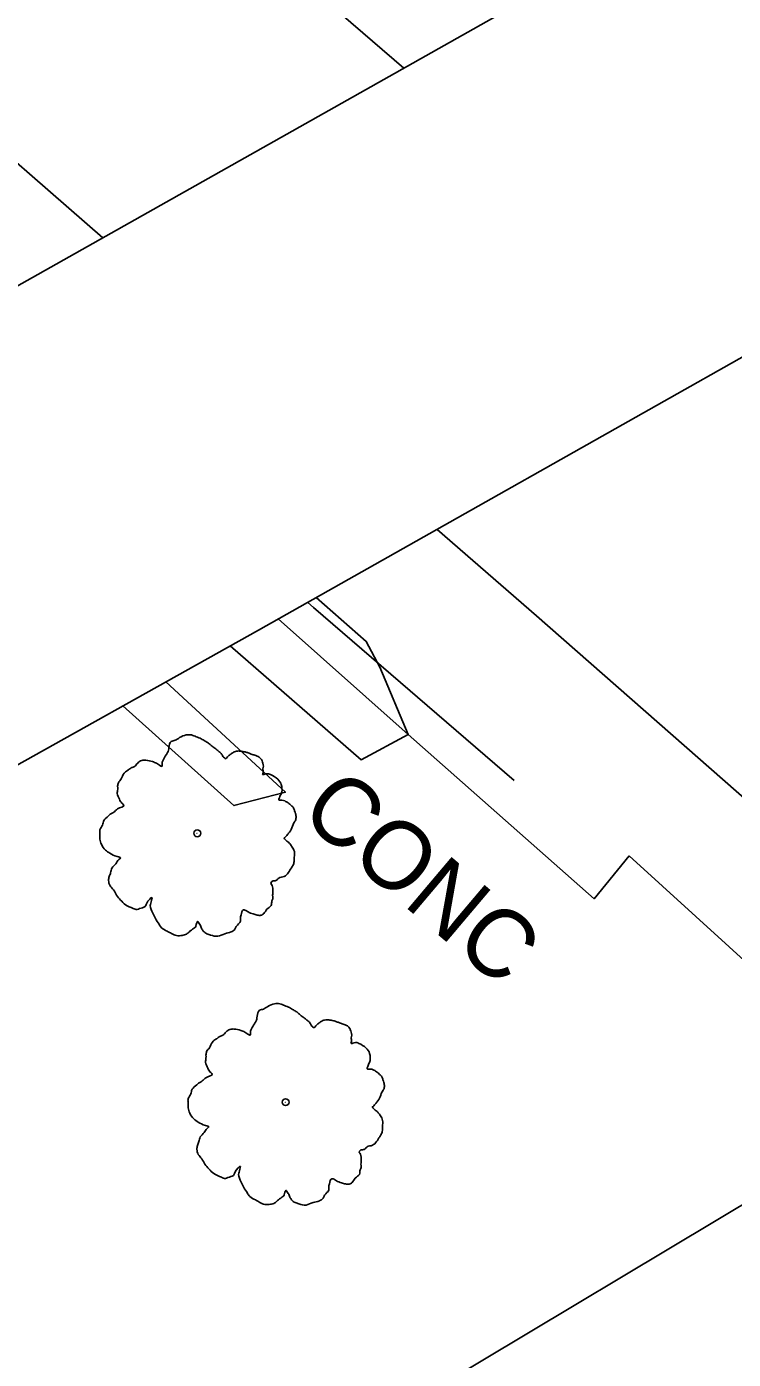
# Model space of a CAD drawing. Extents: x 2076109 to 2080761, y 592812 to 596750.
# Drawn here: x 2077233.4 to 2077285.2, y 595674.8 to 595772.6 of the extents above; entities that cross this region are included whole.
import ezdxf

# ---------------------------------------------------------------- set-up
doc = ezdxf.new("R2010")
doc.units = 0
for name, color, linetype in [('Default', 7, 'Continuous'), ('RD_EX_Bridge', 7, 'Continuous'), ('RD_EX_Conc', 7, 'Continuous'), ('RD_EX_Conc_txCode', 7, 'Continuous'), ('RD_EX_GuardRail', 7, 'Continuous'), ('RD_EX_Misc', 7, 'Continuous'), ('RD_EX_Road', 7, 'Continuous'), ('RD_EX_UT', 7, 'Continuous'), ('RD_EX_VEG', 7, 'Continuous')]:
    doc.layers.add(name, color=color, linetype=linetype)

msp = doc.modelspace()

# ---------------------------------------------------------------- linework, layer by layer
at = {"layer": 'Default'}
msp.add_arc((2035586.697, 547847.965), 63546.515, 48.5011873, 49.29231256, dxfattribs=at)
msp.add_arc((2035586.697, 547847.965), 63546.515, 48.5011873, 49.29231256, dxfattribs=at)
at = {"layer": 'RD_EX_Bridge'}
msp.add_lwpolyline([(2077182.691, 595725.558), (2077226.255, 595749.947), (2077278.629, 595779.435), (2077318.688, 595801.87), (2077370.979, 595831.152), (2077414.589, 595855.594), (2077438.976, 595834.259), (2077395.397, 595809.745), (2077342.887, 595780.396), (2077302.728, 595757.837), (2077250.382, 595728.313), (2077206.947, 595704.058)], close=True, dxfattribs=at)
msp.add_lwpolyline([(2077182.691, 595725.558), (2077226.255, 595749.947), (2077278.629, 595779.435), (2077318.688, 595801.87), (2077370.979, 595831.152), (2077414.589, 595855.594), (2077438.976, 595834.259), (2077395.397, 595809.745), (2077342.887, 595780.396), (2077302.728, 595757.837), (2077250.382, 595728.313), (2077206.947, 595704.058)], close=True, dxfattribs=at)
at = {"layer": 'RD_EX_Conc'}
for points in [[(2077251.831, 595729.131), (2077261.361, 595720.667), (2077257.913, 595718.805), (2077248.302, 595727.152)], [(2077251.831, 595729.131), (2077261.361, 595720.667), (2077257.913, 595718.805), (2077248.302, 595727.152)], [(2077243.58, 595724.515), (2077252.348, 595716.428), (2077248.572, 595715.442), (2077240.424, 595722.752)], [(2077243.58, 595724.515), (2077252.348, 595716.428), (2077248.572, 595715.442), (2077240.424, 595722.752)]]:
    msp.add_lwpolyline(points, dxfattribs=at)
at = {"layer": 'RD_EX_GuardRail'}
msp.add_lwpolyline([(2077253.991, 595730.349), (2077254.423, 595729.975), (2077269.145, 595717.286)], dxfattribs=at)
msp.add_lwpolyline([(2077253.991, 595730.349), (2077254.423, 595729.975), (2077269.145, 595717.286)], dxfattribs=at)
at = {"layer": 'RD_EX_Misc'}
for points in [[(2076740.943, 596217.329), (2076779.876, 596183.766), (2076827.317, 596143.014), (2076861.064, 596114.091), (2076898.336, 596082.262), (2076930.168, 596054.828), (2076977.991, 596013.659), (2077013.095, 595983.674), (2077050.747, 595951.153), (2077080.277, 595925.677), (2077141.218, 595873.032), (2077167.07, 595850.498), (2077217.753, 595806.944), (2077236.465, 595790.711), (2077261.034, 595769.528)], [(2076740.943, 596217.329), (2076779.876, 596183.766), (2076827.317, 596143.014), (2076861.064, 596114.091), (2076898.336, 596082.262), (2076930.168, 596054.828), (2076977.991, 596013.659), (2077013.095, 595983.674), (2077050.747, 595951.153), (2077080.277, 595925.677), (2077141.218, 595873.032), (2077167.07, 595850.498), (2077217.753, 595806.944), (2077236.465, 595790.711), (2077261.034, 595769.528)], [(2077238.942, 595757.089), (2077227.218, 595767.306), (2077200.966, 595789.857), (2077174.304, 595812.849), (2077143.562, 595839.448), (2077119.234, 595860.41), (2077093.272, 595882.761), (2077072.458, 595900.642), (2077047.169, 595922.374), (2077020.069, 595945.554), (2076995.162, 595967.193), (2076973.205, 595985.954), (2076950.941, 596005.114), (2076925.457, 596027.104), (2076903.871, 596045.596), (2076877.623, 596068.098), (2076855.077, 596087.36), (2076831.502, 596107.635), (2076806.015, 596129.351), (2076775.579, 596155.551), (2076743.515, 596183.091), (2076721.01, 596202.456)], [(2077238.942, 595757.089), (2077227.218, 595767.306), (2077200.966, 595789.857), (2077174.304, 595812.849), (2077143.562, 595839.448), (2077119.234, 595860.41), (2077093.272, 595882.761), (2077072.458, 595900.642), (2077047.169, 595922.374), (2077020.069, 595945.554), (2076995.162, 595967.193), (2076973.205, 595985.954), (2076950.941, 596005.114), (2076925.457, 596027.104), (2076903.871, 596045.596), (2076877.623, 596068.098), (2076855.077, 596087.36), (2076831.502, 596107.635), (2076806.015, 596129.351), (2076775.579, 596155.551), (2076743.515, 596183.091), (2076721.01, 596202.456)], [(2077294.469, 595708.577), (2077270.768, 595729.355), (2077263.484, 595735.703)], [(2077294.469, 595708.577), (2077270.768, 595729.355), (2077263.484, 595735.703)]]:
    msp.add_lwpolyline(points, dxfattribs=at)
at = {"layer": 'RD_EX_Road'}
for points in [[(2077277.578, 595711.76), (2077274.998, 595708.61), (2077261.361, 595720.667), (2077259.291, 595725.609), (2077258.28, 595727.485), (2077254.611, 595730.699)], [(2077277.578, 595711.76), (2077274.998, 595708.61), (2077261.361, 595720.667), (2077259.291, 595725.609), (2077258.28, 595727.485), (2077254.611, 595730.699)], [(2077277.578, 595711.76), (2077294.436, 595696.437)], [(2077277.578, 595711.76), (2077294.436, 595696.437)]]:
    msp.add_lwpolyline(points, dxfattribs=at)
at = {"layer": 'RD_EX_UT'}
msp.add_line((2077214.8, 595643.674), (2077512.893, 595821.921), dxfattribs=at)
msp.add_line((2077214.8, 595643.674), (2077512.893, 595821.921), dxfattribs=at)
at = {"layer": 'RD_EX_VEG'}
for centre, radius in [((2077245.885, 595713.416), 0.25), ((2077245.885, 595713.416), 0.25), ((2077245.864, 595713.41), 0.0001), ((2077245.864, 595713.41), 0.0001), ((2077252.366, 595693.701), 0.25), ((2077252.366, 595693.701), 0.25), ((2077252.345, 595693.695), 0.0001), ((2077252.345, 595693.695), 0.0001)]:
    msp.add_circle(centre, radius, dxfattribs=at)
for points in [[(2077250.628, 595718.791), (2077250.416, 595719.004), (2077250.104, 595719.138), (2077249.849, 595719.224), (2077249.629, 595719.313), (2077249.393, 595719.382), (2077249.051, 595719.443), (2077248.75, 595719.437), (2077248.493, 595719.327), (2077248.309, 595719.188), (2077248.093, 595719.011), (2077247.98, 595718.878), (2077247.869, 595718.94), (2077247.77, 595719.056), (2077247.629, 595719.275), (2077247.438, 595719.437), (2077247.248, 595719.599), (2077246.965, 595719.806), (2077246.699, 595720.033), (2077246.457, 595720.173), (2077246.177, 595720.345), (2077245.811, 595720.493), (2077245.463, 595720.624), (2077245.073, 595720.628), (2077244.575, 595720.428), (2077244.253, 595720.243), (2077243.977, 595720.149), (2077243.8, 595719.71), (2077243.706, 595719.33), (2077243.596, 595719.161), (2077243.378, 595718.789), (2077243.308, 595718.553), (2077243.274, 595718.32), (2077243.201, 595718.349), (2077242.883, 595718.554), (2077242.59, 595718.672), (2077242.12, 595718.776), (2077241.803, 595718.75), (2077241.517, 595718.568), (2077241.271, 595718.317), (2077241.065, 595718.23), (2077240.83, 595718.069), (2077240.763, 595718.028), (2077240.514, 595717.813), (2077240.299, 595717.405), (2077240.091, 595717.123), (2077240.041, 595716.87), (2077240.042, 595716.64), (2077240.013, 595716.336), (2077240.172, 595715.906), (2077240.355, 595715.619), (2077240.491, 595715.471), (2077240.034, 595715.203), (2077239.769, 595714.969), (2077239.415, 595714.746), (2077239.367, 595714.688), (2077239.021, 595714.359), (2077238.925, 595714.014), (2077238.739, 595713.68), (2077238.727, 595713.396), (2077238.742, 595712.989), (2077238.844, 595712.607), (2077239.143, 595712.188), (2077239.464, 595711.949), (2077240.015, 595711.709), (2077240.254, 595711.605), (2077240.122, 595711.488), (2077239.898, 595711.186), (2077239.623, 595710.862), (2077239.527, 595710.518), (2077239.425, 595710.244), (2077239.377, 595709.956), (2077239.479, 595709.574), (2077239.735, 595709.258), (2077239.962, 595708.869), (2077240.256, 595708.52), (2077240.62, 595708.177), (2077241.174, 595707.903), (2077241.465, 595707.82), (2077241.654, 595707.889), (2077242.049, 595708.045), (2077242.157, 595708.249), (2077242.564, 595708.689), (2077242.527, 595708.491), (2077242.434, 595708.112), (2077242.62, 595707.559), (2077242.812, 595707.167), (2077243.076, 595706.745), (2077243.256, 595706.494), (2077243.666, 595706.244), (2077244.001, 595706.058), (2077244.367, 595705.91), (2077244.774, 595705.925), (2077245.085, 595706.022), (2077245.301, 595706.199), (2077245.601, 595706.436), (2077245.752, 595706.536)], [(2077250.628, 595718.791), (2077250.416, 595719.004), (2077250.104, 595719.138), (2077249.849, 595719.224), (2077249.629, 595719.313), (2077249.393, 595719.382), (2077249.051, 595719.443), (2077248.75, 595719.437), (2077248.493, 595719.327), (2077248.309, 595719.188), (2077248.093, 595719.011), (2077247.98, 595718.878), (2077247.869, 595718.94), (2077247.77, 595719.056), (2077247.629, 595719.275), (2077247.438, 595719.437), (2077247.248, 595719.599), (2077246.965, 595719.806), (2077246.699, 595720.033), (2077246.457, 595720.173), (2077246.177, 595720.345), (2077245.811, 595720.493), (2077245.463, 595720.624), (2077245.073, 595720.628), (2077244.575, 595720.428), (2077244.253, 595720.243), (2077243.977, 595720.149), (2077243.8, 595719.71), (2077243.706, 595719.33), (2077243.596, 595719.161), (2077243.378, 595718.789), (2077243.308, 595718.553), (2077243.274, 595718.32), (2077243.201, 595718.349), (2077242.883, 595718.554), (2077242.59, 595718.672), (2077242.12, 595718.776), (2077241.803, 595718.75), (2077241.517, 595718.568), (2077241.271, 595718.317), (2077241.065, 595718.23), (2077240.83, 595718.069), (2077240.763, 595718.028), (2077240.514, 595717.813), (2077240.299, 595717.405), (2077240.091, 595717.123), (2077240.041, 595716.87), (2077240.042, 595716.64), (2077240.013, 595716.336), (2077240.172, 595715.906), (2077240.355, 595715.619), (2077240.491, 595715.471), (2077240.034, 595715.203), (2077239.769, 595714.969), (2077239.415, 595714.746), (2077239.367, 595714.688), (2077239.021, 595714.359), (2077238.925, 595714.014), (2077238.739, 595713.68), (2077238.727, 595713.396), (2077238.742, 595712.989), (2077238.844, 595712.607), (2077239.143, 595712.188), (2077239.464, 595711.949), (2077240.015, 595711.709), (2077240.254, 595711.605), (2077240.122, 595711.488), (2077239.898, 595711.186), (2077239.623, 595710.862), (2077239.527, 595710.518), (2077239.425, 595710.244), (2077239.377, 595709.956), (2077239.479, 595709.574), (2077239.735, 595709.258), (2077239.962, 595708.869), (2077240.256, 595708.52), (2077240.62, 595708.177), (2077241.174, 595707.903), (2077241.465, 595707.82), (2077241.654, 595707.889), (2077242.049, 595708.045), (2077242.157, 595708.249), (2077242.564, 595708.689), (2077242.527, 595708.491), (2077242.434, 595708.112), (2077242.62, 595707.559), (2077242.812, 595707.167), (2077243.076, 595706.745), (2077243.256, 595706.494), (2077243.666, 595706.244), (2077244.001, 595706.058), (2077244.367, 595705.91), (2077244.774, 595705.925), (2077245.085, 595706.022), (2077245.301, 595706.199), (2077245.601, 595706.436), (2077245.752, 595706.536)], [(2077245.752, 595706.536), (2077245.809, 595706.718), (2077245.932, 595706.941), (2077245.973, 595706.873), (2077246.074, 595706.722), (2077246.203, 595706.449), (2077246.326, 595706.246), (2077246.589, 595706.055), (2077246.863, 595705.953), (2077247.384, 595705.871), (2077247.901, 595706.054), (2077248.369, 595706.181), (2077248.637, 595706.38), (2077248.745, 595706.584), (2077249.049, 595706.981), (2077249.059, 595707.3), (2077249.102, 595707.428), (2077249.284, 595707.797), (2077249.374, 595707.787), (2077249.616, 595707.647), (2077249.982, 595707.499), (2077250.273, 595707.416), (2077250.557, 595707.404), (2077250.76, 595707.527), (2077251, 595707.848), (2077251.297, 595708.12), (2077251.337, 595708.283), (2077251.358, 595708.462), (2077251.43, 595708.663), (2077251.413, 595708.874), (2077251.434, 595709.053), (2077251.423, 595709.194), (2077251.425, 595709.389), (2077251.373, 595709.597), (2077251.291, 595709.733), (2077251.35, 595709.879), (2077251.593, 595709.934), (2077251.696, 595709.978), (2077251.861, 595710.133), (2077252.259, 595710.254), (2077252.556, 595710.526), (2077252.793, 595710.882), (2077252.933, 595711.124), (2077252.997, 595711.431), (2077253.007, 595711.751), (2077253.025, 595711.965), (2077252.972, 595712.173), (2077252.806, 595712.479), (2077252.648, 595712.679), (2077252.381, 595712.905), (2077252.261, 595713.073), (2077252.313, 595713.095), (2077252.41, 595713.209), (2077252.588, 595713.419), (2077252.822, 595713.81), (2077253.032, 595714.288), (2077253.048, 595714.307), (2077253.133, 595714.562), (2077253.092, 595714.86), (2077253.023, 595715.049), (2077252.952, 595715.274), (2077252.778, 595715.455), (2077252.549, 595715.649), (2077252.307, 595715.789), (2077252.09, 595715.842), (2077251.876, 595715.861), (2077251.916, 595716.023), (2077252.034, 595716.317), (2077252.093, 595716.463), (2077252.092, 595716.693), (2077252.05, 595716.991), (2077251.789, 595717.378), (2077251.264, 595717.726), (2077250.906, 595717.768), (2077250.679, 595717.731), (2077250.722, 595717.859), (2077250.699, 595718.141), (2077250.736, 595718.339), (2077250.684, 595718.547), (2077250.634, 595718.721), (2077250.59, 595718.823)], [(2077245.752, 595706.536), (2077245.809, 595706.718), (2077245.932, 595706.941), (2077245.973, 595706.873), (2077246.074, 595706.722), (2077246.203, 595706.449), (2077246.326, 595706.246), (2077246.589, 595706.055), (2077246.863, 595705.953), (2077247.384, 595705.871), (2077247.901, 595706.054), (2077248.369, 595706.181), (2077248.637, 595706.38), (2077248.745, 595706.584), (2077249.049, 595706.981), (2077249.059, 595707.3), (2077249.102, 595707.428), (2077249.284, 595707.797), (2077249.374, 595707.787), (2077249.616, 595707.647), (2077249.982, 595707.499), (2077250.273, 595707.416), (2077250.557, 595707.404), (2077250.76, 595707.527), (2077251, 595707.848), (2077251.297, 595708.12), (2077251.337, 595708.283), (2077251.358, 595708.462), (2077251.43, 595708.663), (2077251.413, 595708.874), (2077251.434, 595709.053), (2077251.423, 595709.194), (2077251.425, 595709.389), (2077251.373, 595709.597), (2077251.291, 595709.733), (2077251.35, 595709.879), (2077251.593, 595709.934), (2077251.696, 595709.978), (2077251.861, 595710.133), (2077252.259, 595710.254), (2077252.556, 595710.526), (2077252.793, 595710.882), (2077252.933, 595711.124), (2077252.997, 595711.431), (2077253.007, 595711.751), (2077253.025, 595711.965), (2077252.972, 595712.173), (2077252.806, 595712.479), (2077252.648, 595712.679), (2077252.381, 595712.905), (2077252.261, 595713.073), (2077252.313, 595713.095), (2077252.41, 595713.209), (2077252.588, 595713.419), (2077252.822, 595713.81), (2077253.032, 595714.288), (2077253.048, 595714.307), (2077253.133, 595714.562), (2077253.092, 595714.86), (2077253.023, 595715.049), (2077252.952, 595715.274), (2077252.778, 595715.455), (2077252.549, 595715.649), (2077252.307, 595715.789), (2077252.09, 595715.842), (2077251.876, 595715.861), (2077251.916, 595716.023), (2077252.034, 595716.317), (2077252.093, 595716.463), (2077252.092, 595716.693), (2077252.05, 595716.991), (2077251.789, 595717.378), (2077251.264, 595717.726), (2077250.906, 595717.768), (2077250.679, 595717.731), (2077250.722, 595717.859), (2077250.699, 595718.141), (2077250.736, 595718.339), (2077250.684, 595718.547), (2077250.634, 595718.721), (2077250.59, 595718.823)], [(2077257.109, 595699.076), (2077256.897, 595699.29), (2077256.585, 595699.424), (2077256.33, 595699.51), (2077256.11, 595699.598), (2077255.874, 595699.668), (2077255.532, 595699.729), (2077255.231, 595699.722), (2077254.974, 595699.613), (2077254.79, 595699.474), (2077254.574, 595699.297), (2077254.461, 595699.163), (2077254.35, 595699.225), (2077254.251, 595699.341), (2077254.11, 595699.56), (2077253.919, 595699.722), (2077253.729, 595699.884), (2077253.446, 595700.092), (2077253.18, 595700.318), (2077252.938, 595700.458), (2077252.658, 595700.631), (2077252.292, 595700.778), (2077251.944, 595700.91), (2077251.554, 595700.913), (2077251.056, 595700.714), (2077250.734, 595700.528), (2077250.458, 595700.435), (2077250.281, 595699.995), (2077250.187, 595699.615), (2077250.077, 595699.447), (2077249.859, 595699.074), (2077249.789, 595698.838), (2077249.755, 595698.605), (2077249.682, 595698.635), (2077249.364, 595698.839), (2077249.071, 595698.957), (2077248.601, 595699.061), (2077248.284, 595699.036), (2077247.998, 595698.853), (2077247.752, 595698.602), (2077247.547, 595698.515), (2077247.311, 595698.354), (2077247.244, 595698.313), (2077246.995, 595698.098), (2077246.78, 595697.691), (2077246.572, 595697.408), (2077246.522, 595697.156), (2077246.523, 595696.925), (2077246.494, 595696.622), (2077246.653, 595696.191), (2077246.836, 595695.905), (2077246.972, 595695.756), (2077246.515, 595695.489), (2077246.25, 595695.255), (2077245.896, 595695.031), (2077245.848, 595694.974), (2077245.502, 595694.644), (2077245.406, 595694.3), (2077245.22, 595693.966), (2077245.208, 595693.681), (2077245.223, 595693.274), (2077245.325, 595692.893), (2077245.624, 595692.474), (2077245.945, 595692.234), (2077246.496, 595691.995), (2077246.735, 595691.89), (2077246.603, 595691.773), (2077246.379, 595691.471), (2077246.104, 595691.148), (2077246.008, 595690.803), (2077245.906, 595690.529), (2077245.858, 595690.241), (2077245.96, 595689.86), (2077246.216, 595689.543), (2077246.443, 595689.154), (2077246.737, 595688.806), (2077247.101, 595688.463), (2077247.655, 595688.188), (2077247.946, 595688.106), (2077248.135, 595688.174), (2077248.53, 595688.33), (2077248.638, 595688.534), (2077249.045, 595688.975), (2077249.008, 595688.777), (2077248.915, 595688.397), (2077249.101, 595687.845), (2077249.293, 595687.452), (2077249.557, 595687.031), (2077249.737, 595686.779), (2077250.147, 595686.529), (2077250.482, 595686.343), (2077250.848, 595686.196), (2077251.255, 595686.211), (2077251.566, 595686.307), (2077251.782, 595686.484), (2077252.082, 595686.721), (2077252.233, 595686.822)], [(2077257.109, 595699.076), (2077256.897, 595699.29), (2077256.585, 595699.424), (2077256.33, 595699.51), (2077256.11, 595699.598), (2077255.874, 595699.668), (2077255.532, 595699.729), (2077255.231, 595699.722), (2077254.974, 595699.613), (2077254.79, 595699.474), (2077254.574, 595699.297), (2077254.461, 595699.163), (2077254.35, 595699.225), (2077254.251, 595699.341), (2077254.11, 595699.56), (2077253.919, 595699.722), (2077253.729, 595699.884), (2077253.446, 595700.092), (2077253.18, 595700.318), (2077252.938, 595700.458), (2077252.658, 595700.631), (2077252.292, 595700.778), (2077251.944, 595700.91), (2077251.554, 595700.913), (2077251.056, 595700.714), (2077250.734, 595700.528), (2077250.458, 595700.435), (2077250.281, 595699.995), (2077250.187, 595699.615), (2077250.077, 595699.447), (2077249.859, 595699.074), (2077249.789, 595698.838), (2077249.755, 595698.605), (2077249.682, 595698.635), (2077249.364, 595698.839), (2077249.071, 595698.957), (2077248.601, 595699.061), (2077248.284, 595699.036), (2077247.998, 595698.853), (2077247.752, 595698.602), (2077247.547, 595698.515), (2077247.311, 595698.354), (2077247.244, 595698.313), (2077246.995, 595698.098), (2077246.78, 595697.691), (2077246.572, 595697.408), (2077246.522, 595697.156), (2077246.523, 595696.925), (2077246.494, 595696.622), (2077246.653, 595696.191), (2077246.836, 595695.905), (2077246.972, 595695.756), (2077246.515, 595695.489), (2077246.25, 595695.255), (2077245.896, 595695.031), (2077245.848, 595694.974), (2077245.502, 595694.644), (2077245.406, 595694.3), (2077245.22, 595693.966), (2077245.208, 595693.681), (2077245.223, 595693.274), (2077245.325, 595692.893), (2077245.624, 595692.474), (2077245.945, 595692.234), (2077246.496, 595691.995), (2077246.735, 595691.89), (2077246.603, 595691.773), (2077246.379, 595691.471), (2077246.104, 595691.148), (2077246.008, 595690.803), (2077245.906, 595690.529), (2077245.858, 595690.241), (2077245.96, 595689.86), (2077246.216, 595689.543), (2077246.443, 595689.154), (2077246.737, 595688.806), (2077247.101, 595688.463), (2077247.655, 595688.188), (2077247.946, 595688.106), (2077248.135, 595688.174), (2077248.53, 595688.33), (2077248.638, 595688.534), (2077249.045, 595688.975), (2077249.008, 595688.777), (2077248.915, 595688.397), (2077249.101, 595687.845), (2077249.293, 595687.452), (2077249.557, 595687.031), (2077249.737, 595686.779), (2077250.147, 595686.529), (2077250.482, 595686.343), (2077250.848, 595686.196), (2077251.255, 595686.211), (2077251.566, 595686.307), (2077251.782, 595686.484), (2077252.082, 595686.721), (2077252.233, 595686.822)], [(2077252.233, 595686.822), (2077252.29, 595687.004), (2077252.413, 595687.226), (2077252.454, 595687.159), (2077252.555, 595687.007), (2077252.684, 595686.734), (2077252.807, 595686.531), (2077253.07, 595686.34), (2077253.344, 595686.238), (2077253.865, 595686.156), (2077254.382, 595686.34), (2077254.85, 595686.466), (2077255.118, 595686.665), (2077255.226, 595686.869), (2077255.53, 595687.266), (2077255.54, 595687.586), (2077255.583, 595687.713), (2077255.766, 595688.083), (2077255.855, 595688.072), (2077256.097, 595687.932), (2077256.463, 595687.785), (2077256.754, 595687.702), (2077257.038, 595687.689), (2077257.241, 595687.812), (2077257.481, 595688.133), (2077257.778, 595688.405), (2077257.818, 595688.568), (2077257.839, 595688.747), (2077257.911, 595688.948), (2077257.894, 595689.159), (2077257.915, 595689.338), (2077257.904, 595689.479), (2077257.906, 595689.674), (2077257.854, 595689.883), (2077257.772, 595690.018), (2077257.831, 595690.164), (2077258.074, 595690.22), (2077258.177, 595690.263), (2077258.342, 595690.419), (2077258.74, 595690.539), (2077259.037, 595690.812), (2077259.274, 595691.168), (2077259.414, 595691.409), (2077259.478, 595691.716), (2077259.488, 595692.036), (2077259.506, 595692.25), (2077259.453, 595692.459), (2077259.287, 595692.764), (2077259.129, 595692.964), (2077258.862, 595693.191), (2077258.742, 595693.358), (2077258.794, 595693.38), (2077258.891, 595693.494), (2077259.069, 595693.704), (2077259.303, 595694.095), (2077259.513, 595694.573), (2077259.529, 595694.592), (2077259.614, 595694.847), (2077259.573, 595695.145), (2077259.504, 595695.334), (2077259.433, 595695.559), (2077259.259, 595695.74), (2077259.03, 595695.934), (2077258.788, 595696.074), (2077258.571, 595696.128), (2077258.357, 595696.146), (2077258.397, 595696.309), (2077258.515, 595696.602), (2077258.574, 595696.748), (2077258.573, 595696.979), (2077258.532, 595697.277), (2077258.27, 595697.663), (2077257.745, 595698.011), (2077257.387, 595698.053), (2077257.16, 595698.017), (2077257.203, 595698.144), (2077257.18, 595698.426), (2077257.217, 595698.624), (2077257.165, 595698.833), (2077257.115, 595699.006), (2077257.071, 595699.109)], [(2077252.233, 595686.822), (2077252.29, 595687.004), (2077252.413, 595687.226), (2077252.454, 595687.159), (2077252.555, 595687.007), (2077252.684, 595686.734), (2077252.807, 595686.531), (2077253.07, 595686.34), (2077253.344, 595686.238), (2077253.865, 595686.156), (2077254.382, 595686.34), (2077254.85, 595686.466), (2077255.118, 595686.665), (2077255.226, 595686.869), (2077255.53, 595687.266), (2077255.54, 595687.586), (2077255.583, 595687.713), (2077255.766, 595688.083), (2077255.855, 595688.072), (2077256.097, 595687.932), (2077256.463, 595687.785), (2077256.754, 595687.702), (2077257.038, 595687.689), (2077257.241, 595687.812), (2077257.481, 595688.133), (2077257.778, 595688.405), (2077257.818, 595688.568), (2077257.839, 595688.747), (2077257.911, 595688.948), (2077257.894, 595689.159), (2077257.915, 595689.338), (2077257.904, 595689.479), (2077257.906, 595689.674), (2077257.854, 595689.883), (2077257.772, 595690.018), (2077257.831, 595690.164), (2077258.074, 595690.22), (2077258.177, 595690.263), (2077258.342, 595690.419), (2077258.74, 595690.539), (2077259.037, 595690.812), (2077259.274, 595691.168), (2077259.414, 595691.409), (2077259.478, 595691.716), (2077259.488, 595692.036), (2077259.506, 595692.25), (2077259.453, 595692.459), (2077259.287, 595692.764), (2077259.129, 595692.964), (2077258.862, 595693.191), (2077258.742, 595693.358), (2077258.794, 595693.38), (2077258.891, 595693.494), (2077259.069, 595693.704), (2077259.303, 595694.095), (2077259.513, 595694.573), (2077259.529, 595694.592), (2077259.614, 595694.847), (2077259.573, 595695.145), (2077259.504, 595695.334), (2077259.433, 595695.559), (2077259.259, 595695.74), (2077259.03, 595695.934), (2077258.788, 595696.074), (2077258.571, 595696.128), (2077258.357, 595696.146), (2077258.397, 595696.309), (2077258.515, 595696.602), (2077258.574, 595696.748), (2077258.573, 595696.979), (2077258.532, 595697.277), (2077258.27, 595697.663), (2077257.745, 595698.011), (2077257.387, 595698.053), (2077257.16, 595698.017), (2077257.203, 595698.144), (2077257.18, 595698.426), (2077257.217, 595698.624), (2077257.165, 595698.833), (2077257.115, 595699.006), (2077257.071, 595699.109)]]:
    msp.add_spline(points, degree=3, dxfattribs=at)

# ---------------------------------------------------------------- texts
at = {"layer": 'RD_EX_Conc_txCode'}
msp.add_text('CONC', height=5, rotation=319.75923, dxfattribs=at).set_placement((2077253.239, 595714.694))
msp.add_text('CONC', height=5, rotation=319.75923, dxfattribs=at).set_placement((2077253.239, 595714.694))

doc.saveas('drawing.dxf')
